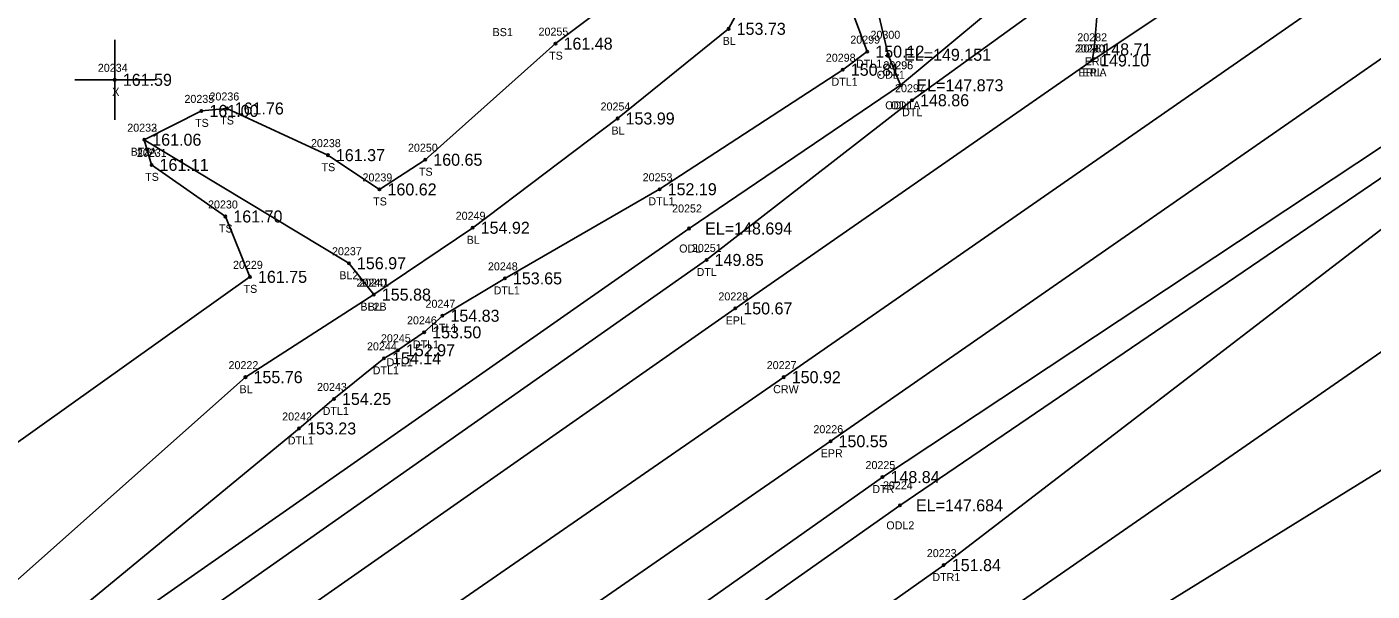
# Model space of a CAD drawing. Extents: x 2449605 to 2452431, y 1012876 to 1014922.
# Drawn here: x 2450467.1 to 2450635.2, y 1013571.4 to 1013641.9 of the extents above; entities that cross this region are included whole.
import ezdxf

# ---------------------------------------------------------------- set-up
doc = ezdxf.new("R2010")
doc.units = 0
for name, color, linetype in [('RD_DTM_BkLn1', 7, 'Continuous'), ('RD_DTM_BkLn2', 7, 'Continuous'), ('RD_DTM_BkLn_txCode', 7, 'Continuous'), ('RD_EX_H2O', 7, 'Continuous'), ('RD_EX_H2O_txCode', 7, 'Continuous'), ('RD_EX_Misc', 7, 'Continuous'), ('RD_EX_Misc_txCode', 7, 'Continuous'), ('RD_EX_Road', 7, 'Continuous'), ('RD_EX_Road_txCode', 7, 'Continuous'), ('RD_EX_TX_H2O_ELEV', 7, 'Continuous'), ('RD_EX_TX_Misc_ELEV', 7, 'Continuous'), ('RD_EX_TX_Road_ELEV', 7, 'Continuous'), ('RD_HC_Survey_ELEV', 7, 'Continuous'), ('RD_HC_Survey_txCode', 7, 'Continuous'), ('RD_SMD_Locator', 7, 'Continuous')]:
    doc.layers.add(name, color=color, linetype=linetype)

msp = doc.modelspace()

# ---------------------------------------------------------------- linework, layer by layer
at = {"layer": 'RD_DTM_BkLn1'}
for points in [[(2449680.58, 1012985.87), (2449759.39, 1013040.31), (2449841.07, 1013097.15), (2449921.06, 1013152.87), (2450001.23, 1013208.89), (2450080.46, 1013264.17), (2450161.02, 1013320.22), (2450242.03, 1013376.29), (2450324.02, 1013432.88), (2450405.2, 1013489.3), (2450483.11, 1013543.86), (2450561.65, 1013598.14), (2450642.32, 1013654.18), (2450739.61, 1013721.61), (2450817.44, 1013775.86), (2450896.72, 1013831.42), (2450912.5, 1013842.34)], [(2450327.03, 1013465.64), (2450385.25, 1013515.48), (2450463.3, 1013570.54), (2450494.41, 1013598.14), (2450510.44, 1013608.45), (2450522.79, 1013616.8), (2450540.89, 1013630.45), (2450554.77, 1013641.65), (2450558.87, 1013649.29), (2450554.61, 1013662.77), (2450554.85, 1013667.72), (2450553.11, 1013671.81), (2450543.9, 1013678.22), (2450519.79, 1013695.83), (2450496.34, 1013716.91)], [(2450481.76, 1013627.8), (2450507.33, 1013612.37), (2450510.44, 1013608.45)]]:
    msp.add_lwpolyline(points, dxfattribs=at)
at = {"layer": 'RD_DTM_BkLn2'}
for points in [[(2450301.63, 1013463.11), (2450375.81, 1013524.05), (2450456.92, 1013583.6), (2450494.97, 1013610.67), (2450491.89, 1013618.21), (2450482.67, 1013624.66), (2450481.76, 1013627.8), (2450488.9, 1013631.4), (2450492.06, 1013631.7), (2450504.7, 1013625.87), (2450511.15, 1013621.59), (2450516.87, 1013625.3), (2450533.14, 1013639.8), (2450547.95, 1013650.98), (2450547.85, 1013655.2), (2450545.34, 1013659.85), (2450542.55, 1013665.51), (2450510.99, 1013691), (2450491.93, 1013709.82)], [(2450412.23, 1013445.13), (2450426.44, 1013458.74), (2450478.83, 1013491.33), (2450509.44, 1013509.8), (2450583.06, 1013564.41), (2450665.69, 1013621.68), (2450761.87, 1013688.24)], [(2450412.23, 1013445.13), (2450429.68, 1013454.01), (2450482, 1013483.09), (2450515.13, 1013504.99), (2450586.83, 1013555.92), (2450673.54, 1013609.55), (2450768.32, 1013681.57)]]:
    msp.add_lwpolyline(points, dxfattribs=at)
at = {"layer": 'RD_EX_H2O'}
for points in [[(2450167.46, 1013291.72), (2450167.1, 1013295.75), (2450175.19, 1013302.21), (2450253.51, 1013357.72), (2450334.87, 1013415.7), (2450415.19, 1013473.64), (2450493.27, 1013528.65), (2450573.99, 1013585.66), (2450651, 1013636.62), (2450748.48, 1013707.64), (2450786.48, 1013731.51)], [(2450167.46, 1013291.72), (2450171.71, 1013290.19), (2450180.8, 1013296.66), (2450259.89, 1013349.14), (2450344.33, 1013402.02), (2450412.23, 1013445.13), (2450424.15, 1013461.12), (2450474.5, 1013497.19), (2450500.92, 1013517.59), (2450581.65, 1013574.66), (2450655.67, 1013631.45), (2450753.63, 1013700.7), (2450792.21, 1013722.47), (2450790.93, 1013725.57), (2450786.48, 1013731.51)], [(2450169.6, 1013293.28), (2450177.31, 1013300.27), (2450255.34, 1013355.6), (2450337.16, 1013412.65), (2450417.79, 1013470.31), (2450495.24, 1013525.07), (2450576.17, 1013582.13), (2450653.09, 1013634.44), (2450750.18, 1013705.23), (2450772.07, 1013717.13), (2450787.49, 1013726.73)], [(2450576.23, 1013634.6), (2450574.68, 1013638.41), (2450572.88, 1013646.24), (2450569.09, 1013662.85), (2450566.49, 1013670.48), (2450565.77, 1013673.93)], [(2450086.85, 1013301.88), (2450146.88, 1013340.5), (2450228.43, 1013395.92), (2450309.72, 1013451.69), (2450392.54, 1013506.78), (2450470.72, 1013561.36), (2450549.83, 1013616.71), (2450576.23, 1013634.6), (2450592.79, 1013648.4), (2450595.89, 1013651.3)], [(2450469.06, 1013565.35), (2450501.1, 1013591.73), (2450505.46, 1013595.42), (2450511.71, 1013600.49), (2450513.45, 1013601.5), (2450516.73, 1013603.74), (2450519.01, 1013605.81), (2450526.82, 1013610.48), (2450546.15, 1013621.61), (2450569.03, 1013636.54), (2450572.09, 1013638.8), (2450568.91, 1013647.37)], [(2450082.81, 1013302.86), (2450086.85, 1013297.03), (2450148.02, 1013337.87), (2450230.55, 1013392.65), (2450311.52, 1013448.88), (2450394.54, 1013504.43), (2450473.16, 1013557.42), (2450552.01, 1013612.78), (2450577.68, 1013632.73), (2450594.53, 1013644.88)]]:
    msp.add_lwpolyline(points, dxfattribs=at)
at = {"layer": 'RD_EX_Misc'}
for p, q in [((2450478.08, 1013630.28), (2450478.08, 1013640.28)), ((2450473.08, 1013635.28), (2450483.08, 1013635.28))]:
    msp.add_line(p, q, dxfattribs=at)
at = {"layer": 'RD_EX_Road'}
for points in [[(2449674.89, 1012994.69), (2449752.35, 1013048.28), (2449834.92, 1013105.96), (2449914.72, 1013161.11), (2449995.66, 1013217.59), (2450075.29, 1013272.9), (2450081.34, 1013277.24), (2450093.41, 1013285.64), (2450155.49, 1013328.69), (2450236.05, 1013384.7), (2450317.88, 1013441.24), (2450398.87, 1013497.28), (2450477.09, 1013551.76), (2450555.6, 1013606.73), (2450600.18, 1013637.7), (2450618.08, 1013649.65), (2450627.95, 1013656.57), (2450636.43, 1013662.28), (2450733.79, 1013730.39), (2450811.43, 1013784.18), (2450891.39, 1013839.9), (2450907.04, 1013850.14)], [(2449685.94, 1012977.62), (2449764.81, 1013032.3), (2449846, 1013088.39), (2449925.85, 1013144.07), (2450006.8, 1013200.56), (2450086.45, 1013256.14), (2450125.67, 1013283.43), (2450163.55, 1013309.93), (2450166.36, 1013312.09), (2450247.44, 1013367.98), (2450329.19, 1013424.41), (2450410.32, 1013481.09), (2450488.38, 1013535.38), (2450567.5, 1013590.14), (2450648.09, 1013646.13), (2450745.08, 1013713.3), (2450823, 1013767.39), (2450902.19, 1013823.2), (2450918.14, 1013833.95)], [(2450600.18, 1013637.7), (2450600.45, 1013639.09), (2450600.98, 1013645.64), (2450599.3, 1013654.26), (2450593.51, 1013662.68), (2450535.8, 1013705.85), (2450505.59, 1013726.88)]]:
    msp.add_lwpolyline(points, dxfattribs=at)
at = {"layer": 'RD_SMD_Locator'}
for centre in [(2450554.77, 1013641.65), (2450533.14, 1013639.8), (2450572.09, 1013638.8), (2450600.45, 1013639.09), (2450574.68, 1013638.41), (2450600.18, 1013637.7), (2450600.18, 1013637.7), (2450569.03, 1013636.54), (2450478.08, 1013635.28), (2450576.23, 1013634.6), (2450576.23, 1013634.6), (2450577.68, 1013632.73), (2450488.9, 1013631.4), (2450492.06, 1013631.7), (2450540.89, 1013630.45), (2450481.76, 1013627.8), (2450481.76, 1013627.8), (2450504.7, 1013625.87), (2450516.87, 1013625.3), (2450482.67, 1013624.66), (2450511.15, 1013621.59), (2450546.15, 1013621.61), (2450491.89, 1013618.21), (2450522.79, 1013616.8), (2450549.83, 1013616.71), (2450507.33, 1013612.37), (2450552.01, 1013612.78), (2450494.97, 1013610.67), (2450526.82, 1013610.48), (2450510.44, 1013608.45), (2450510.44, 1013608.45), (2450519.01, 1013605.81), (2450555.6, 1013606.73), (2450516.73, 1013603.74), (2450511.71, 1013600.49), (2450513.45, 1013601.5), (2450494.41, 1013598.14), (2450561.65, 1013598.14), (2450505.46, 1013595.42), (2450501.1, 1013591.73), (2450567.5, 1013590.14), (2450573.99, 1013585.66), (2450576.17, 1013582.13), (2450581.65, 1013574.66)]:
    msp.add_circle(centre, 0.15, dxfattribs=at)

# ---------------------------------------------------------------- texts
at = {"layer": 'RD_DTM_BkLn_txCode'}
for s, p in [('BS1', (2450525.28, 1013640.74)), ('20255', (2450531.02, 1013640.8)), ('BL', (2450554.02, 1013639.65)), ('TS', (2450532.34, 1013637.8)), ('20235', (2450486.78, 1013632.4)), ('20236', (2450489.91, 1013632.7)), ('20254', (2450538.77, 1013631.45)), ('TS', (2450491.26, 1013629.7)), ('20232', (2450479.64, 1013628.8)), ('20233', (2450479.64, 1013628.8)), ('TS', (2450488.11, 1013629.4)), ('BL', (2450540.13, 1013628.45)), ('20238', (2450502.59, 1013626.87)), ('20250', (2450514.71, 1013626.3)), ('BL2A', (2450480.06, 1013625.8)), ('20231', (2450480.84, 1013625.66)), ('TS', (2450480.96, 1013625.8)), ('TS', (2450503.91, 1013623.87)), ('TS', (2450516.08, 1013623.3)), ('TS', (2450481.87, 1013622.66)), ('20239', (2450509.03, 1013622.59)), ('TS', (2450510.36, 1013619.59)), ('20230', (2450489.73, 1013619.21)), ('20249', (2450520.67, 1013617.8)), ('TS', (2450491.1, 1013616.21)), ('BL', (2450522.04, 1013614.8)), ('20237', (2450505.22, 1013613.37)), ('20229', (2450492.85, 1013611.67)), ('BL2', (2450506.13, 1013610.37)), ('20240', (2450508.28, 1013609.45)), ('20241', (2450508.6, 1013609.45)), ('TS', (2450494.17, 1013608.67)), ('BL2B', (2450508.76, 1013606.45)), ('BL', (2450509.68, 1013606.45)), ('20222', (2450492.29, 1013599.14)), ('BL', (2450493.66, 1013596.14))]:
    msp.add_text(s, height=1, dxfattribs=at).set_placement(p)
at = {"layer": 'RD_EX_H2O_txCode'}
for s, p in [('20299', (2450569.97, 1013639.8)), ('20300', (2450572.49, 1013640.41)), ('20298', (2450566.91, 1013637.54)), ('DTL1', (2450570.68, 1013636.8)), ('20296', (2450574.09, 1013636.6)), ('20295', (2450574.11, 1013636.6)), ('DTL1', (2450567.62, 1013634.54)), ('ODL1', (2450573.28, 1013635.41)), ('20297', (2450575.56, 1013633.73)), ('ODL1A', (2450574.33, 1013631.6)), ('ODL', (2450574.98, 1013631.6)), ('DTL', (2450576.44, 1013630.73)), ('20253', (2450544.03, 1013622.61)), ('DTL1', (2450544.74, 1013619.61)), ('20252', (2450547.71, 1013618.71)), ('ODL', (2450548.59, 1013613.71)), ('20251', (2450550.18, 1013613.78)), ('20248', (2450524.7, 1013611.48)), ('DTL', (2450550.77, 1013610.78)), ('DTL1', (2450525.41, 1013608.48)), ('20247', (2450516.9, 1013606.81)), ('20246', (2450514.59, 1013604.74)), ('DTL1', (2450517.6, 1013603.81)), ('20244', (2450509.59, 1013601.49)), ('20245', (2450511.33, 1013602.5)), ('DTL1', (2450515.32, 1013601.74)), ('DTL1', (2450512.04, 1013599.5)), ('DTL1', (2450510.3, 1013598.49)), ('20243', (2450503.35, 1013596.42)), ('20242', (2450498.99, 1013592.73)), ('DTL1', (2450504.05, 1013593.42)), ('DTL1', (2450499.69, 1013589.73)), ('20225', (2450571.87, 1013586.66)), ('20224', (2450574.05, 1013584.13)), ('DTR', (2450572.72, 1013583.66)), ('ODL2', (2450574.47, 1013579.13)), ('20223', (2450579.53, 1013575.66)), ('DTR1', (2450580.22, 1013572.66))]:
    msp.add_text(s, height=1, dxfattribs=at).set_placement(p)
at = {"layer": 'RD_EX_Misc_txCode'}
for s, p in [('20234', (2450475.96, 1013636.28)), ('X', (2450477.76, 1013633.28))]:
    msp.add_text(s, height=1, dxfattribs=at).set_placement(p)
at = {"layer": 'RD_EX_Road_txCode'}
for s, p in [('20282', (2450598.33, 1013640.09)), ('20280', (2450598.03, 1013638.7)), ('20281', (2450598.35, 1013638.7)), ('ERL', (2450599.25, 1013637.09)), ('ERLA', (2450598.49, 1013635.7)), ('EPL', (2450598.98, 1013635.7)), ('20228', (2450553.49, 1013607.73)), ('EPL', (2450554.4, 1013604.73)), ('20226', (2450565.36, 1013591.14)), ('EPR', (2450566.27, 1013588.14))]:
    msp.add_text(s, height=1, dxfattribs=at).set_placement(p)
at = {"layer": 'RD_EX_TX_H2O_ELEV'}
for s, p in [('150.12', (2450573.09, 1013638.05)), ('EL=149.151', (2450576.68, 1013637.66)), ('150.81', (2450570.03, 1013635.79)), ('EL=147.873', (2450578.23, 1013633.85)), ('EL=147.873', (2450578.23, 1013633.85)), ('148.86', (2450578.68, 1013631.98)), ('152.19', (2450547.15, 1013620.86)), ('EL=148.694', (2450551.83, 1013615.96)), ('149.85', (2450553.01, 1013612.03)), ('153.65', (2450527.82, 1013609.73)), ('154.83', (2450520.01, 1013605.06)), ('153.50', (2450517.73, 1013602.99)), ('152.97', (2450514.45, 1013600.75)), ('154.14', (2450512.71, 1013599.74)), ('154.25', (2450506.46, 1013594.67)), ('153.23', (2450502.1, 1013590.98)), ('148.84', (2450574.99, 1013584.91)), ('EL=147.684', (2450578.17, 1013581.38)), ('151.84', (2450582.65, 1013573.91))]:
    msp.add_text(s, height=1.5, dxfattribs=at).set_placement(p)
at = {"layer": 'RD_EX_TX_Misc_ELEV'}
for s, p in [('153.73', (2450555.77, 1013640.9)), ('161.48', (2450534.14, 1013639.05)), ('161.59', (2450479.08, 1013634.53)), ('161.00', (2450489.9, 1013630.65)), ('161.76', (2450493.06, 1013630.95)), ('153.99', (2450541.89, 1013629.7)), ('161.06', (2450482.76, 1013627.05)), ('161.06', (2450482.76, 1013627.05)), ('161.11', (2450483.67, 1013623.91)), ('161.37', (2450505.7, 1013625.12)), ('160.65', (2450517.87, 1013624.55)), ('160.62', (2450512.15, 1013620.84)), ('161.70', (2450492.89, 1013617.46)), ('154.92', (2450523.79, 1013616.05)), ('156.97', (2450508.33, 1013611.62)), ('161.75', (2450495.97, 1013609.92)), ('155.88', (2450511.44, 1013607.7)), ('155.88', (2450511.44, 1013607.7)), ('155.76', (2450495.41, 1013597.39))]:
    msp.add_text(s, height=1.5, dxfattribs=at).set_placement(p)
at = {"layer": 'RD_EX_TX_Road_ELEV'}
for s, p in [('148.71', (2450601.45, 1013638.34)), ('149.10', (2450601.18, 1013636.95)), ('149.10', (2450601.18, 1013636.95)), ('150.67', (2450556.6, 1013605.98)), ('150.55', (2450568.5, 1013589.39))]:
    msp.add_text(s, height=1.5, dxfattribs=at).set_placement(p)
at = {"layer": 'RD_HC_Survey_ELEV'}
msp.add_text('150.92', height=1.5, dxfattribs=at).set_placement((2450562.65, 1013597.39))
at = {"layer": 'RD_HC_Survey_txCode'}
for s, p in [('20227', (2450559.53, 1013599.14)), ('CRW', (2450560.33, 1013596.14))]:
    msp.add_text(s, height=1, dxfattribs=at).set_placement(p)

doc.saveas('drawing.dxf')
